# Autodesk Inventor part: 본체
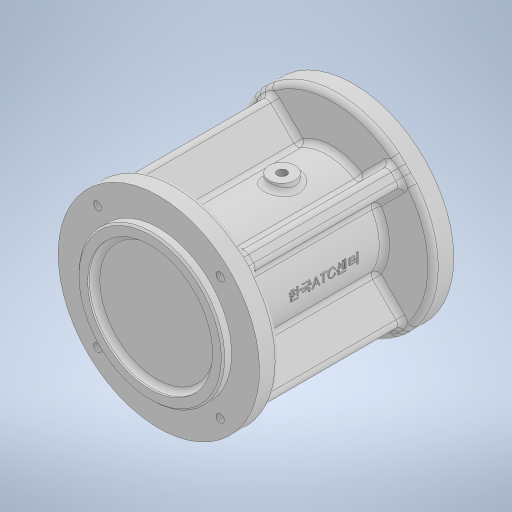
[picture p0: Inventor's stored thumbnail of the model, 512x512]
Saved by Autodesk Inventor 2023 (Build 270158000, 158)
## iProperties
Created: 2024-10
Part Number: 본체
Material: 일반
Document SubType Name: Modeling
Designer: home
Density: 1 g/cm^3
Appearance: 기본값
Author: home
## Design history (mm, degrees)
sketch "스케치2"
  geometry: L1 (0, 75)-(0, -75); L2 (10.5, 64)-(10.5, 61); L3 (10.5, 61)-(16, 61); L4 (16, 61)-(16, 57); L5 (16, 57)-(18, 57); L6 (18, 57)-(18, 39); L7 (18, 39)-(21, 39); L8 (21, 39)-(21, 27); L9 (21, 27)-(30, 27); L10 (30, 27)-(30, -27); L11 (30, -27)-(21, -27); L12 (21, -27)-(21, -43); L13 (10.5, 64)-(0, 64); L14 (21, -43)-(36, -43); L15 (36, -43)-(36, -46); L16 (36, -46)-(0, -46); 8 further points
  constraints: 32 end point, 11 perpendicular, 7 midpoint, 3 vertical, 2 horizontal, 2 point on line, 1 coincident, 1 horizontal alignment
  dimensions: "d0" = 21 diameter of point (10.5, 62.5) L1; "d1" = 3 distance between parallel lines of L3 L13; "d2" = 32 diameter of point (16, 59) L1; "d3" = 4 distance of L3.end L4.end; "d5" = 36 diameter of L6 L1; "d6" = 18 distance of L5.end L6.end; "d7" = 42 diameter of L8 L1; "d9" = 42 diameter of L12 L1; "d11" = 150 distance of L1.start L1.end; "d12" = 72 diameter of point (36, -44.5) L1; "d14" = 3 distance of L14.end L15.end; "d15" = 16 distance of L11.end L12.end; "d32" = 54 distance of L9.end L10.end; "d33" = 60 diameter of L10 L1; "d34" = 82 distance from line of L14 point (19.5, 39)
revolve "회전1" sketch "스케치2" stored, may be unused: angle "d20" = 90 deg
sketch "스케치3"
  geometry: L1 (0, 95.391)-(0, -95.391); L2 (0, 76)-(42, 76); L3 (42, 76)-(42, 71); L4 (42, 71)-(58, 71); L5 (58, 71)-(58, 59); L6 (58, 59)-(23, 59); L7 (23, 59)-(23, 44); L8 (0, -46)-(42, -46); L9 (42, -46)-(42, -41); L10 (42, -41)-(58, -41); L11 (58, -41)-(58, -29); L12 (-36, -46)-(36, -46) reference; L13 (23, 44)-(27, 44); L14 (30, 41)-(30, -29); L15 (30, -29)-(58, -29); A1 r 3 centre (27, 41) between (30, 41) and (27, 44); 7 further points
  constraints: 28 end point, 10 perpendicular, 5 midpoint, 4 point on line, 3 horizontal, 2 point on circle, 2 tangent, 1 centre point, 1 coincident, 1 horizontal alignment, 1 vertical
  dimensions: "d21" = 5 distance of L2.end L3.end; "d22" = 12 distance of L4.end L5.end; "d23" = 122 distance between parallel lines of L8 L2; "d24" = 12 distance of L10.end L11.end; "d25" = 5 distance of L8.end L9.end; "d26" = 116 diameter of point (58, 65) L1; "d27" = 84 diameter of point (42, 73.5) L1; "d28" = 116 diameter of point (58, -35) L1; "d29" = 84 diameter of L9 L1; "d30" = 46 diameter of L7 L1; "d112" = 60 diameter of L14 L1; "d113" = 15 distance from line of point (25, 44) L6; "d114" = 141.39081 distance from line of L1.start L12; "d159" = 3 radius of A1 (derived)
revolve "회전2" sketch "스케치3" stored, may be unused: angle "d35" = 360 deg
sketch "스케치4"
  geometry: C1 r 36 at (0, 0); 1 further point
  constraints: 1 centre point, 1 coincident
  dimensions: "d36" = 72 diameter of C1
extrude "돌출1" cut sketch "스케치4" distance "d37" = 4; taper "d38" = 0 deg
sketch "스케치5"
  geometry: L1 (0, 75)-(0, -75); L2 (10.5, 64)-(10.5, 61); L3 (10.5, 61)-(15.4, 61); L4 (16, 60.4)-(16, 57); L5 (16, 57)-(18, 57); L6 (18, 57)-(18, 39); L7 (18, 39)-(20.4, 39); L8 (21, 38.4)-(21, 27); L9 (21, 27)-(25, 27); L10 (25, 27)-(25, -27); L11 (25, -27)-(21, -27); L12 (21, -27)-(21, -43); L13 (10.5, 64)-(0, 64); L14 (21, -43)-(36, -43); L15 (36, -43)-(36, -46); L16 (36, -46)-(0, -46); L17 (-42, -46)-(42, -46) reference; A1 r 0.6 centre (15.4, 60.4) between (16, 60.4) and (15.4, 61); A2 r 0.6 centre (20.4, 38.4) between (21, 38.4) and (20.4, 39); 11 further points
  constraints: 32 end point, 11 perpendicular, 7 midpoint, 6 point on line, 4 point on circle, 4 tangent, 3 vertical, 2 centre point, 2 coincident, 2 horizontal, 2 horizontal alignment, 1 equal radius
  dimensions: "d39" = 21 diameter of point (10.5, 62.5) L1; "d40" = 3 distance between parallel lines of L3 L13; "d41" = 32 diameter of point (16, 58.7) L1; "d42" = 4 distance of point (16, 61) L4.end; "d43" = 36 diameter of L6 L1; "d44" = 18 distance of L5.end L6.end; "d45" = 42 diameter of L8 L1; "d46" = 42 diameter of L12 L1; "d47" = 150 distance of L1.start L1.end; "d48" = 72 diameter of point (36, -44.5) L1; "d49" = 3 distance of L14.end L15.end; "d50" = 16 distance of L11.end L12.end; "d51" = 54 distance of L9.end L10.end; "d52" = 50 diameter of L10 L1; "d53" = 82 distance from line of L14 point (19.2, 39); "d147" = 0.6 radius of A1
revolve "회전3" sketch "스케치5" stored, may be unused: angle "d54" = 360 deg
sketch "스케치7" dims "d55" = 100
  geometry: L1 (0, 0)-(-66.422, 66.422); L2 (0, 0)-(-78.662, 0); C1 r 58 at (0, 0) reference; C2 r 42 at (0, 0) reference; C3 r 36 at (0, 0) reference; C4 r 23 at (0, 0) reference; 2 further points
  constraints: 4 end point, 1 coincident, 1 horizontal, 1 point on line, 3 other
  dimensions: "d79" = 45 deg angle of L2 L1
  node "투영된 루프1"
sketch "스케치8" dims "d66" = 100
  geometry: L1 (0, 0)-(83.546, 0); L2 (0, 0)-(61.692, 61.692); C1 r 10.5 at (0, 0) reference; C2 r 42 at (0, 0) reference; 2 further points
  constraints: 4 end point, 1 coincident, 1 horizontal, 1 point on line, 3 other
  dimensions: "d90" = 45 deg angle of L1 L2
hole "구멍3" sketch "스케치7" diameter "d80" = 4.917; stored, may be unused: countersink angle "d84" = 90 deg, drill point angle "d86" = 118 deg; dims "d81" = 12, "d82" = 4, "d83" = 2, "d85" = 14
hole "구멍4" sketch "스케치8" diameter "d91" = 4.917; stored, may be unused: countersink angle "d95" = 90 deg, drill point angle "d97" = 118 deg; dims "d92" = 12, "d93" = 4, "d94" = 2, "d96" = 14
sketch "스케치9" dims "d101" = 56
  geometry: C1 r 21 at (0, 0) reference; C2 r 36 at (0, 0) reference; 2 further points
  constraints: 2 vertical alignment, 1 coincident, 2 other
hole "구멍5" sketch "스케치9" at (0, 28) diameter "d102" = 4.134; stored, may be unused: countersink angle "d106" = 90 deg, drill point angle "d108" = 118 deg; dims "d103" = 10, "d104" = 4, "d105" = 2, "d107" = 12
node "작업 평면1"
sketch "스케치10"
  geometry: C1 r 7.5 at (0, 0); 1 further point
  constraints: 1 centre point, 1 coincident
  dimensions: "d117" = 15 diameter of C1
extrude "돌출2" join sketch "스케치10" stored distance "d118" = 4; taper "d119" = 0 deg
node "작업 평면2"
sketch "스케치11"
  geometry: C1 r 7.5 at (0, 0); 1 further point
  constraints: 1 centre point, 1 coincident
  dimensions: "d121" = 15 diameter of C1
extrude "돌출3" join sketch "스케치11" stored distance "d122" = 10; taper "d123" = 0 deg
sketch "스케치12"
  geometry: C1 r 7.5 at (0, 0) reference; 1 further point
  constraints: 1 coincident
hole "구멍6" sketch "스케치12" at (0, 0) diameter "d124" = 5.45873; stored, may be unused: countersink angle "d128" = 90 deg, drill point angle "d130" = 118 deg; dims "d125" = 12, "d126" = 4, "d127" = 2, "d129" = 8
node "작업 평면3"
sketch "스케치13"
  geometry: L1 (-59, 54)-(29, 54); L2 (-59, -58)-(-59, 58) reference; L3 (-59, 54)-(-59, 23); L4 (29, 54)-(29, 30); 3 further points
  constraints: 6 end point, 1 horizontal, 1 parallel
  dimensions: "d131" = 54 distance from line of point (0, 0) L1; "d132" = 90 deg angle of L3 L1
feature "리브1" sketch "스케치13" dims "d133" = 1, "d134" = 10, "d135" = 0, "d136" = 0, "d137" = 1, "d138" = 1
chamfer "모따기1" distance "d139" = 1; stored, may be unused: second distance "d140" = 2, angle "d141" = 45 deg
fillet "모깎기1" dims "d142" = 3
fillet "모깎기2" dims "d143" = 3
fillet "모깎기3" dims "d144" = 3
fillet "모깎기4" dims "d145" = 3
fillet "모깎기5" dims "d146" = 3
fillet "모깎기6" dims "d148" = 3
fillet "모깎기7" dims "d149" = 3
chamfer "모따기2" distance "d150" = 1; stored, may be unused: second distance "d151" = 2, angle "d152" = 45 deg
fillet "모깎기8" dims "d153" = 3
node "작업 평면4"
sketch "스케치15"
  geometry: L1 (41, -46)-(-41, -46) reference; 2 further points
  constraints: 1 vertical alignment, 1 other
  dimensions: "d155" = 52 distance from line of L1 point (0, 6)
feature "엠보싱1" sketch "스케치15" dims "d0" = 21, "d1" = 3, "d2" = 32, "d3" = 4, "d5" = 36, "d6" = 18, "d7" = 42, "d9" = 42, "d11" = 150, "d12" = 72, "d14" = 3, "d15" = 16, "d32" = 54, "d33" = 60, "d34" = 82, "d156" = 0.5, "d157" = 0
fillet "모깎기9" dims "d158" = 3
node "솔리드1"
pattern_circular "원형 패턴3" dims angle "d88" = 360 deg
pattern_circular "원형 패턴4" dims angle "d99" = 360 deg
pattern_circular "원형 패턴5" dims angle "d110" = 360 deg
mirror "미러1"
mirror "미러2"
feature "A9D066F2-1C7D-4E18-AEED-F7BC21143FA4" dims "d80" = 4.917, "d81" = 12, "d82" = 4, "d83" = 2, "d84" = 90 deg, "d85" = 14, "d86" = 118 deg
other parameters: "d116" = 34, "d120" = -34
